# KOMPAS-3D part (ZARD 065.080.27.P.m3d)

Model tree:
1. Булева операция:1
2. Булева операция:2
3. Булева операция:3
4. Булева операция:4
5. Булева операция:5
6. Булева операция:6
7. Булева операция:7
8. Булева операция:8
9. Булева операция:9
10. Булева операция:10
11. Булева операция:11
12. Булева операция:12
13. Булева операция:13  (labels: C:\Program Files\ASCON\KOMPAS-3D V13\Sys\graphic.lyt)
